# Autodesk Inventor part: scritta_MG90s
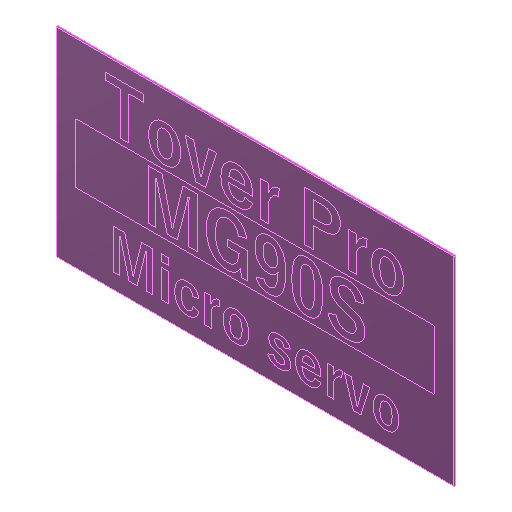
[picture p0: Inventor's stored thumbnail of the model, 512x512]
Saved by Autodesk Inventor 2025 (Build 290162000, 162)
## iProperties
Created: 2018-08
Part Number: scritta_MG90s
Material: Plastica PAEK
Document SubType Name: Modeling
Designer: Ryzen5700u
Density: 1.32 g/cm^3
Appearance: Default
Author: Ryzen5700u
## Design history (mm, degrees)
feature "Твердое тело1"
node "Solido1"
